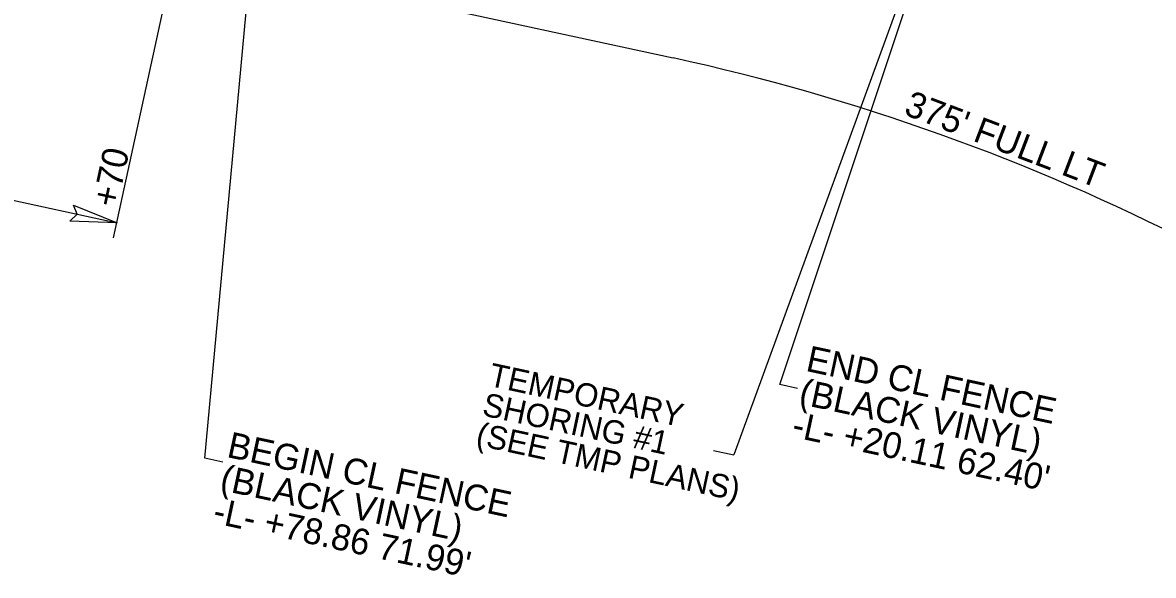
# Model space of a CAD drawing. Extents: x 1762196 to 1766326, y 709922 to 713142.
# Drawn here: x 1762895 to 1763113.4, y 712366.7 to 712473.4 of the extents above; entities that cross this region are included whole.
import ezdxf

# ---------------------------------------------------------------- set-up
doc = ezdxf.new("R2010")
doc.units = 0
for name, color, linetype in [('Prop Dimension', 7, 'Continuous'), ('Prop Fence Chain Link', 7, 'Continuous'), ('Prop Horizontal Alignment', 7, 'Continuous'), ('Prop Lane Lines', 7, 'Continuous'), ('Prop Terminator CELL', 7, 'Continuous')]:
    doc.layers.add(name, color=color, linetype=linetype)

msp = doc.modelspace()

# ---------------------------------------------------------------- linework, layer by layer
at = {"layer": 'Prop Dimension'}
for p, q in [((1762912.54, 712431.86), (1762944.74, 712580.28)), ((1762930.2, 712389.33), (1762943.44, 712532.49)), ((1763078.48, 712516.39), (1763032.33, 712389.96)), ((1763041.21, 712403.56), (1763077.03, 712511.03)), ((1762924.6, 712487.44), (1763020.61, 712466.61)), ((1762815.55, 712455.97), (1762913.27, 712434.77)), ((1763044.65, 712402.81), (1763041.21, 712403.56)), ((1762933.64, 712388.59), (1762930.2, 712389.33)), ((1763028.41, 712390.8), (1763032.33, 712389.96))]:
    msp.add_line(p, q, dxfattribs=at)
msp.add_arc((1762933.05, 712063), 413, 48.0096, 77.7598, dxfattribs=at)
at = {"layer": 'Prop Horizontal Alignment'}
msp.add_arc((1762933.05, 712063), 533, 36.325, 77.7598, dxfattribs=at)
at = {"layer": 'Prop Lane Lines'}
for radius in [539, 527]:
    msp.add_arc((1762933.05, 712063), radius, 36.325, 77.7598, dxfattribs=at)
at = {"layer": 'Prop Terminator CELL'}
msp.add_lwpolyline([(1762904.81, 712438.19), (1762913.27, 712434.77), (1762904.09, 712435.12), (1762905.55, 712436.44)], close=True, dxfattribs=at)

# ---------------------------------------------------------------- texts
at = {"layer": 'Prop Dimension'}
for s, height, rotation, p in [("375' FULL LT", 5, 339.1388, (1763064.98, 712455.76)), ('+70', 5, 77.7598, (1762913.22, 712437.55)), ('TEMPORARY ', 4.5, 347.8639, (1762984.79, 712403.35)), ('SHORING #1', 4.5, 347.8639, (1762983.56, 712397.63)), ('(SEE TMP PLANS)', 4.5, 347.8639, (1762982.33, 712391.91))]:
    msp.add_text(s, height=height, rotation=rotation, dxfattribs=at).set_placement(p)
at = {"layer": 'Prop Fence Chain Link'}
for s, p in [('END CL FENCE', (1763046.06, 712406.22)), ('(BLACK VINYL)', (1763044.7, 712399.86)), ("-L- +20.11 62.40'", (1763043.33, 712393.51)), ('BEGIN CL FENCE', (1762934.25, 712389.59)), ('(BLACK VINYL)', (1762932.88, 712383.24)), ("-L- +78.86 71.99'", (1762931.51, 712376.88))]:
    msp.add_text(s, height=5, rotation=347.8639, dxfattribs=at).set_placement(p)

doc.saveas('drawing.dxf')
